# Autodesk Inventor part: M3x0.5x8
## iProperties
IsCustomPart: 1
Company: 한국ATC센터
Created: 2009-02
Part Number: M3x0.5x8
Material: 강, 연강
Description: 6각머리 태핑 나사
Document SubType Name: Modeling
Standard: KS B 1003
Designer: KYOUNG IL JANG
Standards Organization: KS
Language: ko-KR
Size Designation: M 4 x 12
Categories: <MemberInstance><Categories><Category DisplayName="조임쇠" InternalName="e4da775c-781d-43d5-af7c-5136215cf5a6" Mnemonic="FSTN"><Category DisplayName="볼트" InternalN
Density: 7.86 g/cm^3
Mass: 1.37432 g
Surface Area: 2.584 cm^2
Volume: 0.174849 cm^3
Vendor: CBT Solutions
Author: KYOUNG IL JANG
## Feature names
1. Fillet2
